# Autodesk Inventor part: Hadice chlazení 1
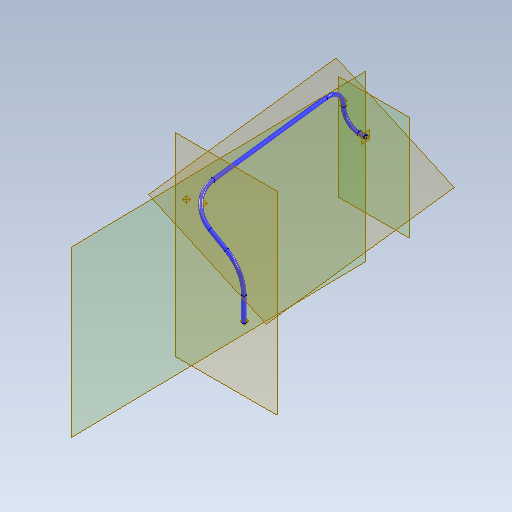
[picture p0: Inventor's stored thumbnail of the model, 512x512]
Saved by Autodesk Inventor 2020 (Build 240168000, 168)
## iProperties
Created: 2025-04
Part Number: Hadice chlazení 1
Material: Polyetylen, S nízkou hustotou
Document SubType Name: Modeling
Designer: doma
Density: 0.894 g/cm^3
Appearance: Modrá – nástěnná malba – lesklá
Author: doma
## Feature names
1. Tažení1
## Parameters: d0 = 15 mm, d3 = 1 deg, d6 = 60 deg, d9 = 8 mm, d10 = 0, d11 = 0
